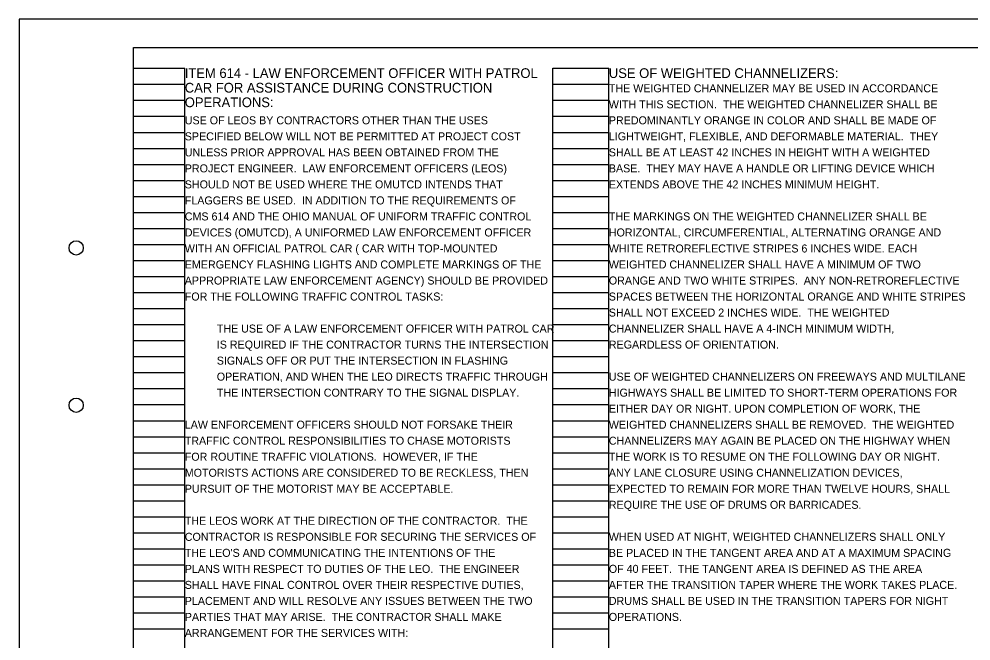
# Model space of a CAD drawing. Extents: x 0 to 34, y 0 to 22.
# Drawn here: x 0 to 16.66, y 11.13 to 22 of the extents above; entities that cross this region are included whole.
import ezdxf

# ---------------------------------------------------------------- set-up
doc = ezdxf.new("R2010")
doc.units = 0
for name, color, linetype in [('BD_P_Text', 7, 'Continuous'), ('SH_Border', 7, 'Continuous'), ('SH_Cut_Line', 7, 'Continuous'), ('SH_Data', 7, 'Continuous')]:
    doc.layers.add(name, color=color, linetype=linetype)

msp = doc.modelspace()

# ---------------------------------------------------------------- linework, layer by layer
at = {"layer": 'SH_Border'}
msp.add_lwpolyline([(2, 21.5), (33.5, 21.5), (33.5, 0.5), (2, 0.5)], close=True, dxfattribs=at)
for centre in [(1, 18), (1, 15.25)]:
    msp.add_circle(centre, 0.125, dxfattribs=at)
at = {"layer": 'SH_Cut_Line'}
msp.add_lwpolyline([(0, 0), (34, 0), (34, 22), (0, 22)], close=True, dxfattribs=at)
at = {"layer": 'SH_Data'}
for p, q in [((2, 0.98), (2, 21.14)), ((2, 21.14), (2.9, 21.14)), ((2.9, 0.98), (2.9, 21.14)), ((9.34, 0.98), (9.34, 21.14)), ((9.34, 21.14), (10.32, 21.14)), ((10.32, 0.98), (10.32, 21.14)), ((2, 20.86), (2.9, 20.86)), ((9.34, 20.86), (10.32, 20.86)), ((2, 20.58), (2.9, 20.58)), ((9.34, 20.58), (10.32, 20.58)), ((2, 20.3), (2.9, 20.3)), ((9.34, 20.3), (10.32, 20.3)), ((2, 20.02), (2.9, 20.02)), ((9.34, 20.02), (10.32, 20.02)), ((2, 19.74), (2.9, 19.74)), ((9.34, 19.74), (10.32, 19.74)), ((2, 19.46), (2.9, 19.46)), ((9.34, 19.46), (10.32, 19.46)), ((2, 19.18), (2.9, 19.18)), ((9.34, 19.18), (10.32, 19.18)), ((2, 18.9), (2.9, 18.9)), ((9.34, 18.9), (10.32, 18.9)), ((2, 18.62), (2.9, 18.62)), ((9.34, 18.62), (10.32, 18.62)), ((2, 18.34), (2.9, 18.34)), ((9.34, 18.34), (10.32, 18.34)), ((2, 18.06), (2.9, 18.06)), ((9.34, 18.06), (10.32, 18.06)), ((2, 17.78), (2.9, 17.78)), ((9.34, 17.78), (10.32, 17.78)), ((2, 17.5), (2.9, 17.5)), ((9.34, 17.5), (10.32, 17.5)), ((2, 17.22), (2.9, 17.22)), ((9.34, 17.22), (10.32, 17.22)), ((2, 16.94), (2.9, 16.94)), ((9.34, 16.94), (10.32, 16.94)), ((2, 16.66), (2.9, 16.66)), ((9.34, 16.66), (10.32, 16.66)), ((2, 16.38), (2.9, 16.38)), ((9.34, 16.38), (10.32, 16.38)), ((2, 16.1), (2.9, 16.1)), ((9.34, 16.1), (10.32, 16.1)), ((2, 15.82), (2.9, 15.82)), ((9.34, 15.82), (10.32, 15.82)), ((2, 15.54), (2.9, 15.54)), ((9.34, 15.54), (10.32, 15.54)), ((2, 15.26), (2.9, 15.26)), ((9.34, 15.26), (10.32, 15.26)), ((2, 14.98), (2.9, 14.98)), ((9.34, 14.98), (10.32, 14.98)), ((2, 14.7), (2.9, 14.7)), ((9.34, 14.7), (10.32, 14.7)), ((2, 14.42), (2.9, 14.42)), ((9.34, 14.42), (10.32, 14.42)), ((2, 14.14), (2.9, 14.14)), ((9.34, 14.14), (10.32, 14.14)), ((2, 13.86), (2.9, 13.86)), ((9.34, 13.86), (10.32, 13.86)), ((2, 13.58), (2.9, 13.58)), ((9.34, 13.58), (10.32, 13.58)), ((2, 13.3), (2.9, 13.3)), ((9.34, 13.3), (10.32, 13.3)), ((2, 13.02), (2.9, 13.02)), ((9.34, 13.02), (10.32, 13.02)), ((2, 12.74), (2.9, 12.74)), ((9.34, 12.74), (10.32, 12.74)), ((2, 12.46), (2.9, 12.46)), ((9.34, 12.46), (10.32, 12.46)), ((2, 12.18), (2.9, 12.18)), ((9.34, 12.18), (10.32, 12.18)), ((2, 11.9), (2.9, 11.9)), ((9.34, 11.9), (10.32, 11.9)), ((2, 11.62), (2.9, 11.62)), ((9.34, 11.62), (10.32, 11.62)), ((2, 11.34), (2.9, 11.34)), ((9.34, 11.34), (10.32, 11.34))]:
    msp.add_line(p, q, dxfattribs=at)

# ---------------------------------------------------------------- texts
at = {"layer": 'BD_P_Text'}
for s, height, p in [('ITEM 614 - LAW ENFORCEMENT OFFICER WITH PATROL ', 0.17, (2.9, 20.97)), ('USE OF WEIGHTED CHANNELIZERS:', 0.17, (10.32, 20.97)), ('CAR FOR ASSISTANCE DURING CONSTRUCTION ', 0.17, (2.9, 20.715)), ('THE WEIGHTED CHANNELIZER MAY BE USED IN ACCORDANCE ', 0.14, (10.32, 20.72)), ('OPERATIONS:', 0.17, (2.9, 20.46)), ('WITH THIS SECTION.  THE WEIGHTED CHANNELIZER SHALL BE ', 0.14, (10.32, 20.44)), ('USE OF LEOS BY CONTRACTORS OTHER THAN THE USES ', 0.14, (2.9, 20.16)), ('PREDOMINANTLY ORANGE IN COLOR AND SHALL BE MADE OF ', 0.14, (10.32, 20.16)), ('SPECIFIED BELOW WILL NOT BE PERMITTED AT PROJECT COST ', 0.14, (2.9, 19.88)), ('LIGHTWEIGHT, FLEXIBLE, AND DEFORMABLE MATERIAL.  THEY ', 0.14, (10.32, 19.88)), ('UNLESS PRIOR APPROVAL HAS BEEN OBTAINED FROM THE ', 0.14, (2.9, 19.6)), ('SHALL BE AT LEAST 42 INCHES IN HEIGHT WITH A WEIGHTED ', 0.14, (10.32, 19.6)), ('PROJECT ENGINEER.  LAW ENFORCEMENT OFFICERS (LEOS) ', 0.14, (2.9, 19.32)), ('BASE.  THEY MAY HAVE A HANDLE OR LIFTING DEVICE WHICH ', 0.14, (10.32, 19.32)), ('SHOULD NOT BE USED WHERE THE OMUTCD INTENDS THAT ', 0.14, (2.9, 19.04)), ('EXTENDS ABOVE THE 42 INCHES MINIMUM HEIGHT.', 0.14, (10.32, 19.04)), ('FLAGGERS BE USED.  IN ADDITION TO THE REQUIREMENTS OF ', 0.14, (2.9, 18.76)), ('CMS 614 AND THE OHIO MANUAL OF UNIFORM TRAFFIC CONTROL ', 0.14, (2.9, 18.48)), ('THE MARKINGS ON THE WEIGHTED CHANNELIZER SHALL BE ', 0.14, (10.32, 18.48)), ('DEVICES (OMUTCD), A UNIFORMED LAW ENFORCEMENT OFFICER ', 0.14, (2.9, 18.2)), ('HORIZONTAL, CIRCUMFERENTIAL, ALTERNATING ORANGE AND ', 0.14, (10.32, 18.2)), ('WITH AN OFFICIAL PATROL CAR ( CAR WITH TOP-MOUNTED ', 0.14, (2.9, 17.92)), ('WHITE RETROREFLECTIVE STRIPES 6 INCHES WIDE. EACH ', 0.14, (10.32, 17.92)), ('EMERGENCY FLASHING LIGHTS AND COMPLETE MARKINGS OF THE ', 0.14, (2.9, 17.64)), ('WEIGHTED CHANNELIZER SHALL HAVE A MINIMUM OF TWO ', 0.14, (10.32, 17.64)), ('APPROPRIATE LAW ENFORCEMENT AGENCY) SHOULD BE PROVIDED ', 0.14, (2.9, 17.36)), ('ORANGE AND TWO WHITE STRIPES.  ANY NON-RETROREFLECTIVE ', 0.14, (10.32, 17.36)), ('FOR THE FOLLOWING TRAFFIC CONTROL TASKS:', 0.14, (2.9, 17.08)), ('SPACES BETWEEN THE HORIZONTAL ORANGE AND WHITE STRIPES ', 0.14, (10.32, 17.08)), ('SHALL NOT EXCEED 2 INCHES WIDE.  THE WEIGHTED ', 0.14, (10.32, 16.8)), ('THE USE OF A LAW ENFORCEMENT OFFICER WITH PATROL CAR', 0.14, (3.46, 16.52)), ('CHANNELIZER SHALL HAVE A 4-INCH MINIMUM WIDTH, ', 0.14, (10.32, 16.52)), ('IS REQUIRED IF THE CONTRACTOR TURNS THE INTERSECTION', 0.14, (3.46, 16.24)), ('REGARDLESS OF ORIENTATION.', 0.14, (10.32, 16.24)), ('SIGNALS OFF OR PUT THE INTERSECTION IN FLASHING', 0.14, (3.46, 15.96)), ('OPERATION, AND WHEN THE LEO DIRECTS TRAFFIC THROUGH', 0.14, (3.46, 15.68)), ('USE OF WEIGHTED CHANNELIZERS ON FREEWAYS AND MULTILANE ', 0.14, (10.32, 15.68)), ('THE INTERSECTION CONTRARY TO THE SIGNAL DISPLAY.', 0.14, (3.46, 15.4)), ('HIGHWAYS SHALL BE LIMITED TO SHORT-TERM OPERATIONS FOR ', 0.14, (10.32, 15.4)), ('EITHER DAY OR NIGHT. UPON COMPLETION OF WORK, THE ', 0.14, (10.32, 15.12)), ('LAW ENFORCEMENT OFFICERS SHOULD NOT FORSAKE THEIR ', 0.14, (2.9, 14.84)), ('WEIGHTED CHANNELIZERS SHALL BE REMOVED.  THE WEIGHTED ', 0.14, (10.32, 14.84)), ('TRAFFIC CONTROL RESPONSIBILITIES TO CHASE MOTORISTS ', 0.14, (2.9, 14.56)), ('CHANNELIZERS MAY AGAIN BE PLACED ON THE HIGHWAY WHEN ', 0.14, (10.32, 14.56)), ('FOR ROUTINE TRAFFIC VIOLATIONS.  HOWEVER, IF THE ', 0.14, (2.9, 14.28)), ('THE WORK IS TO RESUME ON THE FOLLOWING DAY OR NIGHT.  ', 0.14, (10.32, 14.28)), ('MOTORISTS ACTIONS ARE CONSIDERED TO BE RECKLESS, THEN ', 0.14, (2.9, 14)), ('ANY LANE CLOSURE USING CHANNELIZATION DEVICES, ', 0.14, (10.32, 14)), ('PURSUIT OF THE MOTORIST MAY BE ACCEPTABLE.', 0.14, (2.9, 13.72)), ('EXPECTED TO REMAIN FOR MORE THAN TWELVE HOURS, SHALL ', 0.14, (10.32, 13.72)), ('REQUIRE THE USE OF DRUMS OR BARRICADES.', 0.14, (10.32, 13.44)), ('THE LEOS WORK AT THE DIRECTION OF THE CONTRACTOR.  THE ', 0.14, (2.9, 13.16)), ('CONTRACTOR IS RESPONSIBLE FOR SECURING THE SERVICES OF ', 0.14, (2.9, 12.88)), ('WHEN USED AT NIGHT, WEIGHTED CHANNELIZERS SHALL ONLY ', 0.14, (10.32, 12.88)), ("THE LEO'S AND COMMUNICATING THE INTENTIONS OF THE ", 0.14, (2.9, 12.6)), ('BE PLACED IN THE TANGENT AREA AND AT A MAXIMUM SPACING ', 0.14, (10.32, 12.6)), ('PLANS WITH RESPECT TO DUTIES OF THE LEO.  THE ENGINEER ', 0.14, (2.9, 12.32)), ('OF 40 FEET.  THE TANGENT AREA IS DEFINED AS THE AREA ', 0.14, (10.32, 12.32)), ('SHALL HAVE FINAL CONTROL OVER THEIR RESPECTIVE DUTIES, ', 0.14, (2.9, 12.04)), ('AFTER THE TRANSITION TAPER WHERE THE WORK TAKES PLACE. ', 0.14, (10.32, 12.04)), ('PLACEMENT AND WILL RESOLVE ANY ISSUES BETWEEN THE TWO ', 0.14, (2.9, 11.76)), ('DRUMS SHALL BE USED IN THE TRANSITION TAPERS FOR NIGHT ', 0.14, (10.32, 11.76)), ('PARTIES THAT MAY ARISE.  THE CONTRACTOR SHALL MAKE ', 0.14, (2.9, 11.48)), ('OPERATIONS.', 0.14, (10.32, 11.48)), ('ARRANGEMENT FOR THE SERVICES WITH:', 0.14, (2.9, 11.2))]:
    msp.add_text(s, height=height, dxfattribs=at).set_placement(p)

doc.saveas('drawing.dxf')
